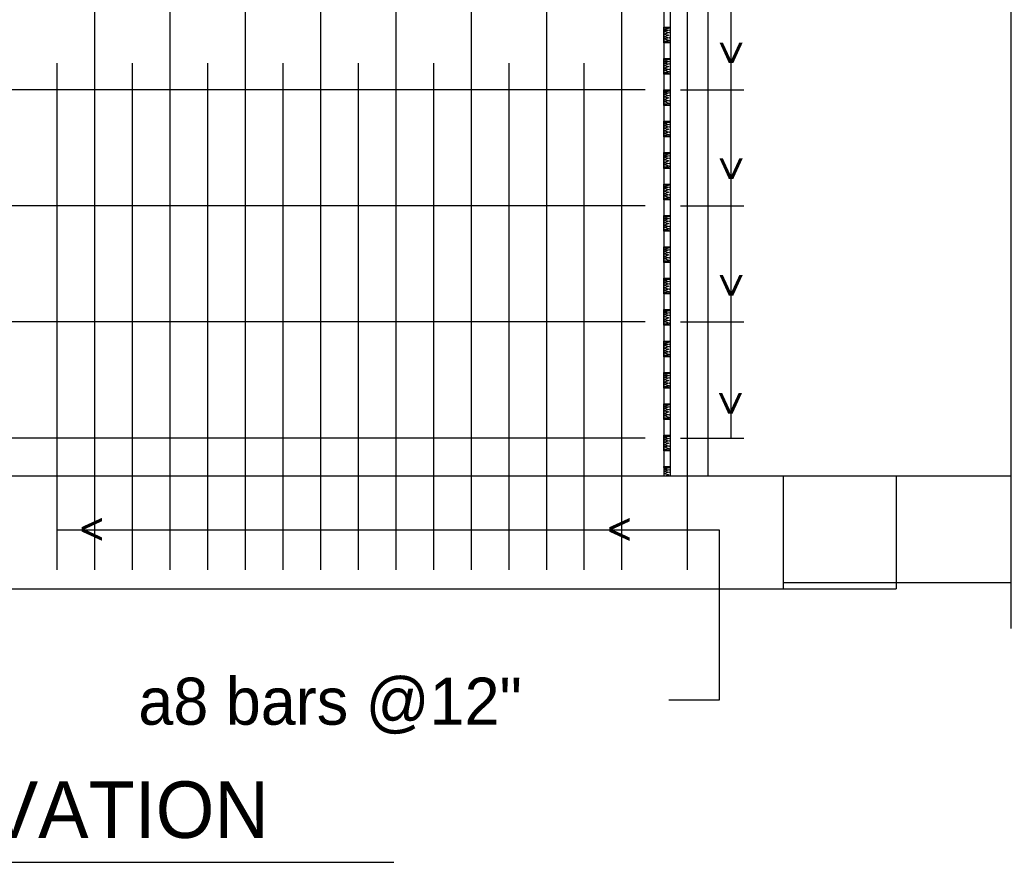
# Model space of a CAD drawing. Extents: x -0.08 to 2.83, y -0.03 to 1.92.
# Drawn here: x 0.6457 to 0.9199, y 0.5697 to 0.8025 of the extents above; entities that cross this region are included whole.
import ezdxf

# ---------------------------------------------------------------- set-up
doc = ezdxf.new("R2010")
doc.units = 0
for name, color, linetype in [('1', 7, 'Continuous'), ('50', 7, 'Continuous'), ('51', 7, 'Continuous'), ('55', 7, 'Continuous'), ('57', 7, 'Continuous')]:
    doc.layers.add(name, color=color, linetype=linetype)

msp = doc.modelspace()

# ---------------------------------------------------------------- linework, layer by layer
at = {"layer": '1'}
for points in [[(0.82387, 0.79621), (0.82387, 0.80055), (0.8256, 0.80055), (0.8256, 0.79621)], [(0.82387, 0.78754), (0.82387, 0.79187), (0.8256, 0.79187), (0.8256, 0.78754)], [(0.82387, 0.77885), (0.82387, 0.78319), (0.8256, 0.78319), (0.8256, 0.77885)], [(0.82387, 0.77017), (0.82387, 0.77451), (0.8256, 0.77451), (0.8256, 0.77017)], [(0.82387, 0.76149), (0.82387, 0.76583), (0.8256, 0.76583), (0.8256, 0.76149)], [(0.82387, 0.75281), (0.82387, 0.75714), (0.8256, 0.75714), (0.8256, 0.75281)], [(0.82387, 0.74413), (0.82387, 0.74847), (0.8256, 0.74847), (0.8256, 0.74413)], [(0.82387, 0.73545), (0.82387, 0.73979), (0.8256, 0.73979), (0.8256, 0.73545)], [(0.82387, 0.72677), (0.82387, 0.7311), (0.8256, 0.7311), (0.8256, 0.72677)], [(0.82387, 0.71809), (0.82387, 0.72243), (0.8256, 0.72243), (0.8256, 0.71809)], [(0.82387, 0.70941), (0.82387, 0.71374), (0.8256, 0.71374), (0.8256, 0.70941)], [(0.82387, 0.70073), (0.82387, 0.70506), (0.8256, 0.70506), (0.8256, 0.70073)], [(0.82387, 0.69204), (0.82387, 0.69639), (0.8256, 0.69639), (0.8256, 0.69204)], [(0.82387, 0.68337), (0.82387, 0.6877), (0.8256, 0.6877), (0.8256, 0.68337)]]:
    msp.add_lwpolyline(points, close=True, dxfattribs=at)
for points in [[(0.82398, 0.80031), (0.8255, 0.80033), (0.82398, 0.7998), (0.82534, 0.79969), (0.82402, 0.79928), (0.82531, 0.79901), (0.82405, 0.79861), (0.82526, 0.79832), (0.82405, 0.79787), (0.82536, 0.79754), (0.82401, 0.7973), (0.82536, 0.79681), (0.82409, 0.79657), (0.82531, 0.79645), (0.82524, 0.79644)], [(0.82398, 0.79163), (0.8255, 0.79164), (0.82398, 0.79112), (0.82534, 0.791), (0.82402, 0.7906), (0.82531, 0.79034), (0.82405, 0.78993), (0.82526, 0.78964), (0.82405, 0.78919), (0.82536, 0.78886), (0.82401, 0.78862), (0.82536, 0.78813), (0.82409, 0.78789), (0.82531, 0.78777), (0.82524, 0.78775)], [(0.82398, 0.78294), (0.8255, 0.78296), (0.82398, 0.78244), (0.82534, 0.78233), (0.82402, 0.78192), (0.82531, 0.78165), (0.82405, 0.78125), (0.82526, 0.78095), (0.82405, 0.7805), (0.82536, 0.78018), (0.82401, 0.77994), (0.82536, 0.77944), (0.82409, 0.77921), (0.82531, 0.77909), (0.82524, 0.77908)], [(0.82398, 0.77427), (0.8255, 0.77429), (0.82398, 0.77376), (0.82534, 0.77364), (0.82402, 0.77324), (0.82531, 0.77297), (0.82405, 0.77257), (0.82526, 0.77228), (0.82405, 0.77183), (0.82536, 0.77149), (0.82401, 0.77126), (0.82536, 0.77077), (0.82409, 0.77053), (0.82531, 0.77041), (0.82524, 0.77039)], [(0.82398, 0.76559), (0.8255, 0.7656), (0.82398, 0.76508), (0.82534, 0.76496), (0.82402, 0.76456), (0.82531, 0.76429), (0.82405, 0.76389), (0.82526, 0.76359), (0.82405, 0.76314), (0.82536, 0.76282), (0.82401, 0.76258), (0.82536, 0.76209), (0.82409, 0.76184), (0.82531, 0.76173), (0.82524, 0.76171)], [(0.82398, 0.7569), (0.8255, 0.75692), (0.82398, 0.7564), (0.82534, 0.75629), (0.82402, 0.75588), (0.82531, 0.75561), (0.82405, 0.75521), (0.82526, 0.75491), (0.82405, 0.75446), (0.82536, 0.75414), (0.82401, 0.75389), (0.82536, 0.7534), (0.82409, 0.75317), (0.82531, 0.75305), (0.82524, 0.75304)], [(0.82398, 0.74823), (0.8255, 0.74824), (0.82398, 0.74772), (0.82534, 0.7476), (0.82402, 0.74719), (0.82531, 0.74693), (0.82405, 0.74653), (0.82526, 0.74624), (0.82405, 0.74579), (0.82536, 0.74545), (0.82401, 0.74522), (0.82536, 0.74473), (0.82409, 0.74449), (0.82531, 0.74437), (0.82524, 0.74435)], [(0.82398, 0.73954), (0.8255, 0.73956), (0.82398, 0.73904), (0.82534, 0.73892), (0.82402, 0.73852), (0.82531, 0.73825), (0.82405, 0.73784), (0.82526, 0.73755), (0.82405, 0.7371), (0.82536, 0.73678), (0.82401, 0.73654), (0.82536, 0.73604), (0.82409, 0.7358), (0.82531, 0.73569), (0.82524, 0.73567)], [(0.82398, 0.73086), (0.8255, 0.73088), (0.82398, 0.73036), (0.82534, 0.73024), (0.82402, 0.72984), (0.82531, 0.72957), (0.82405, 0.72917), (0.82526, 0.72887), (0.82405, 0.72842), (0.82536, 0.72809), (0.82401, 0.72785), (0.82536, 0.72736), (0.82409, 0.72713), (0.82531, 0.72701), (0.82524, 0.72699)], [(0.82398, 0.72219), (0.8255, 0.7222), (0.82398, 0.72168), (0.82534, 0.72156), (0.82402, 0.72115), (0.82531, 0.72089), (0.82405, 0.72049), (0.82526, 0.72019), (0.82405, 0.71974), (0.82536, 0.71941), (0.82401, 0.71918), (0.82536, 0.71869), (0.82409, 0.71844), (0.82531, 0.71833), (0.82524, 0.71831)], [(0.82398, 0.7135), (0.8255, 0.71352), (0.82398, 0.71299), (0.82534, 0.71288), (0.82402, 0.71248), (0.82531, 0.71221), (0.82405, 0.7118), (0.82526, 0.71151), (0.82405, 0.71106), (0.82536, 0.71074), (0.82401, 0.71049), (0.82536, 0.71), (0.82409, 0.70976), (0.82531, 0.70964), (0.82524, 0.70963)], [(0.82398, 0.70482), (0.8255, 0.70484), (0.82398, 0.70432), (0.82534, 0.7042), (0.82402, 0.70379), (0.82531, 0.70353), (0.82405, 0.70313), (0.82526, 0.70283), (0.82405, 0.70238), (0.82536, 0.70205), (0.82401, 0.70181), (0.82536, 0.70132), (0.82409, 0.70109), (0.82531, 0.70097), (0.82524, 0.70095)], [(0.82398, 0.69614), (0.8255, 0.69616), (0.82398, 0.69564), (0.82534, 0.69552), (0.82402, 0.69511), (0.82531, 0.69484), (0.82405, 0.69444), (0.82526, 0.69415), (0.82405, 0.6937), (0.82536, 0.69337), (0.82401, 0.69314), (0.82536, 0.69264), (0.82409, 0.6924), (0.82531, 0.69229), (0.82524, 0.69227)], [(0.82398, 0.68746), (0.8255, 0.68748), (0.82398, 0.68695), (0.82534, 0.68684), (0.82402, 0.68644), (0.82531, 0.68617), (0.82405, 0.68576), (0.82526, 0.68547), (0.82405, 0.68502), (0.82536, 0.68469), (0.82401, 0.68445), (0.82536, 0.68396), (0.82409, 0.68372), (0.82531, 0.6836), (0.82524, 0.68359)], [(0.82387, 0.67877), (0.82387, 0.67902), (0.82552, 0.67902)], [(0.82398, 0.67878), (0.8255, 0.67879), (0.82398, 0.67828), (0.82534, 0.67816), (0.82402, 0.67775), (0.82531, 0.67749), (0.82405, 0.67709), (0.82526, 0.67679), (0.82444, 0.67649)]]:
    msp.add_lwpolyline(points, dxfattribs=at)
at = {"layer": '50'}
for p, q in [((0.83601, 0.99767), (0.83601, 0.67648)), ((0.82385, 0.90749), (0.82385, 0.67648)), ((0.82559, 0.90749), (0.82559, 0.67642)), ((0.91992, 0.63423), (0.91992, 0.81979)), ((0.82385, 0.80125), (0.82385, 0.79516)), ((0.82559, 0.80125), (0.82559, 0.79516)), ((0.82385, 0.80061), (0.82385, 0.79592)), ((0.82559, 0.80061), (0.82559, 0.79592)), ((0.82559, 0.80011), (0.82559, 0.79592)), ((0.82385, 0.79592), (0.82385, 0.79516)), ((0.82559, 0.79592), (0.82559, 0.79516)), ((0.82385, 0.79257), (0.82385, 0.78649)), ((0.82385, 0.79257), (0.82385, 0.78649)), ((0.82559, 0.79257), (0.82559, 0.78649)), ((0.82559, 0.79257), (0.82559, 0.78649)), ((0.82385, 0.79193), (0.82385, 0.78724)), ((0.82559, 0.79193), (0.82559, 0.78724)), ((0.82559, 0.79144), (0.82559, 0.78724)), ((0.82385, 0.78724), (0.82385, 0.78649)), ((0.82559, 0.78724), (0.82559, 0.78649)), ((0.82385, 0.78389), (0.82385, 0.7778)), ((0.82385, 0.78389), (0.82385, 0.7778)), ((0.82385, 0.78389), (0.82385, 0.7778)), ((0.82385, 0.78325), (0.82385, 0.77856)), ((0.82559, 0.78389), (0.82559, 0.7778)), ((0.82559, 0.78389), (0.82559, 0.7778)), ((0.82559, 0.78389), (0.82559, 0.7778)), ((0.82559, 0.78325), (0.82559, 0.77856)), ((0.82559, 0.78275), (0.82559, 0.77856)), ((0.82385, 0.77856), (0.82385, 0.7778)), ((0.82559, 0.77856), (0.82559, 0.7778)), ((0.82385, 0.77457), (0.82385, 0.76988)), ((0.82559, 0.77457), (0.82559, 0.76988)), ((0.82559, 0.77407), (0.82559, 0.76988)), ((0.82385, 0.76988), (0.82385, 0.76912)), ((0.82559, 0.76988), (0.82559, 0.76912)), ((0.82385, 0.76653), (0.82385, 0.76044)), ((0.82385, 0.76589), (0.82385, 0.76119)), ((0.82559, 0.76653), (0.82559, 0.76044)), ((0.82559, 0.76589), (0.82559, 0.76119)), ((0.82559, 0.76539), (0.82559, 0.76119)), ((0.82385, 0.76119), (0.82385, 0.76044)), ((0.82559, 0.76119), (0.82559, 0.76044)), ((0.82385, 0.75784), (0.82385, 0.75176)), ((0.82385, 0.75784), (0.82385, 0.75176)), ((0.82385, 0.75721), (0.82385, 0.75252)), ((0.82559, 0.75784), (0.82559, 0.75176)), ((0.82559, 0.75784), (0.82559, 0.75176)), ((0.82559, 0.75721), (0.82559, 0.75252)), ((0.82559, 0.75671), (0.82559, 0.75252)), ((0.82385, 0.75252), (0.82385, 0.75176)), ((0.82559, 0.75252), (0.82559, 0.75176)), ((0.82385, 0.74917), (0.82385, 0.74308)), ((0.82385, 0.74917), (0.82385, 0.74308)), ((0.82385, 0.74917), (0.82385, 0.74308)), ((0.82559, 0.74917), (0.82559, 0.74308)), ((0.82559, 0.74917), (0.82559, 0.74308)), ((0.82559, 0.74917), (0.82559, 0.74308)), ((0.82385, 0.74853), (0.82385, 0.74384)), ((0.82559, 0.74853), (0.82559, 0.74384)), ((0.82559, 0.74803), (0.82559, 0.74384)), ((0.82385, 0.74384), (0.82385, 0.74308)), ((0.82559, 0.74384), (0.82559, 0.74308)), ((0.82385, 0.73984), (0.82385, 0.73515)), ((0.82559, 0.73984), (0.82559, 0.73515)), ((0.82559, 0.73935), (0.82559, 0.73515)), ((0.82385, 0.73515), (0.82385, 0.7344)), ((0.82559, 0.73515), (0.82559, 0.7344)), ((0.82385, 0.7318), (0.82385, 0.72572)), ((0.82385, 0.73117), (0.82385, 0.72648)), ((0.82559, 0.7318), (0.82559, 0.72572)), ((0.82559, 0.73117), (0.82559, 0.72648)), ((0.82559, 0.73067), (0.82559, 0.72648)), ((0.82385, 0.72648), (0.82385, 0.72572)), ((0.82559, 0.72648), (0.82559, 0.72572)), ((0.82385, 0.72313), (0.82385, 0.71704)), ((0.82385, 0.72313), (0.82385, 0.71704)), ((0.82385, 0.72249), (0.82385, 0.71779)), ((0.82559, 0.72313), (0.82559, 0.71704)), ((0.82559, 0.72313), (0.82559, 0.71704)), ((0.82559, 0.72249), (0.82559, 0.71779)), ((0.82559, 0.72199), (0.82559, 0.71779)), ((0.82385, 0.71779), (0.82385, 0.71704)), ((0.82559, 0.71779), (0.82559, 0.71704)), ((0.82385, 0.71444), (0.82385, 0.70836)), ((0.82385, 0.71444), (0.82385, 0.70836)), ((0.82385, 0.71444), (0.82385, 0.70836)), ((0.82385, 0.7138), (0.82385, 0.70911)), ((0.82559, 0.71444), (0.82559, 0.70836)), ((0.82559, 0.71444), (0.82559, 0.70836)), ((0.82559, 0.71444), (0.82559, 0.70836)), ((0.82559, 0.7138), (0.82559, 0.70911)), ((0.82559, 0.71331), (0.82559, 0.70911)), ((0.82385, 0.70911), (0.82385, 0.70836)), ((0.82559, 0.70911), (0.82559, 0.70836)), ((0.82385, 0.70513), (0.82385, 0.70044)), ((0.82559, 0.70513), (0.82559, 0.70044)), ((0.82559, 0.70463), (0.82559, 0.70044)), ((0.82385, 0.70044), (0.82385, 0.69968)), ((0.82559, 0.70044), (0.82559, 0.69968)), ((0.82385, 0.69709), (0.82385, 0.69099)), ((0.82559, 0.69709), (0.82559, 0.69099)), ((0.82385, 0.69644), (0.82385, 0.69175)), ((0.82559, 0.69644), (0.82559, 0.69175)), ((0.82559, 0.69594), (0.82559, 0.69175)), ((0.82385, 0.69175), (0.82385, 0.69099)), ((0.82559, 0.69175), (0.82559, 0.69099)), ((0.82385, 0.6884), (0.82385, 0.68232)), ((0.82385, 0.6884), (0.82385, 0.68232)), ((0.82559, 0.6884), (0.82559, 0.68232)), ((0.82559, 0.6884), (0.82559, 0.68232)), ((0.82385, 0.68776), (0.82385, 0.68307)), ((0.82559, 0.68776), (0.82559, 0.68307)), ((0.82559, 0.68727), (0.82559, 0.68307)), ((0.82385, 0.68307), (0.82385, 0.68232)), ((0.82559, 0.68307), (0.82559, 0.68232)), ((0.36955, 0.67649), (0.91992, 0.67649)), ((0.82559, 0.67649), (0.82559, 0.67638)), ((0.85684, 0.67648), (0.85684, 0.64523)), ((0.88809, 0.67649), (0.88809, 0.64524)), ((0.36955, 0.64524), (0.88809, 0.64524)), ((0.85684, 0.64697), (0.91992, 0.64697))]:
    msp.add_line(p, q, dxfattribs=at)
at = {"layer": '51'}
for p, q in [((0.81226, 0.65044), (0.81226, 0.98682)), ((0.83039, 0.65044), (0.83039, 0.98682)), ((0.74976, 0.65044), (0.74976, 0.96326)), ((0.77059, 0.65044), (0.77059, 0.96326)), ((0.79143, 0.65044), (0.79143, 0.96326)), ((0.68726, 0.65044), (0.68726, 0.94275)), ((0.70809, 0.65044), (0.70809, 0.94275)), ((0.72893, 0.65044), (0.72893, 0.94275)), ((0.66643, 0.65044), (0.66643, 0.92069)), ((0.65601, 0.65044), (0.65601, 0.7906)), ((0.67684, 0.65044), (0.67684, 0.7906)), ((0.69768, 0.65044), (0.69768, 0.7906)), ((0.71851, 0.65044), (0.71851, 0.7906)), ((0.73934, 0.65044), (0.73934, 0.7906)), ((0.76018, 0.65044), (0.76018, 0.7906)), ((0.78101, 0.65044), (0.78101, 0.7906)), ((0.80184, 0.65044), (0.80184, 0.7906)), ((0.81864, 0.78324), (0.37281, 0.78324)), ((0.82847, 0.78324), (0.84599, 0.78324)), ((0.84122, 0.78325), (0.84122, 0.78325)), ((0.81864, 0.75113), (0.37281, 0.75113)), ((0.82847, 0.75113), (0.84599, 0.75113)), ((0.84122, 0.75113), (0.84122, 0.75113)), ((0.81864, 0.71901), (0.37281, 0.71901)), ((0.82847, 0.71901), (0.84599, 0.71901)), ((0.84122, 0.71901), (0.84122, 0.71901)), ((0.81864, 0.68689), (0.37281, 0.68689)), ((0.82847, 0.68689), (0.84599, 0.68689)), ((0.84122, 0.68689), (0.84122, 0.68689))]:
    msp.add_line(p, q, dxfattribs=at)
at = {"layer": '55'}
for p, q in [((0.84244, 0.68689), (0.84244, 0.97595)), ((0.65601, 0.6615), (0.83918, 0.6615)), ((0.83918, 0.6615), (0.83918, 0.61445)), ((0.83918, 0.61445), (0.82519, 0.61445))]:
    msp.add_line(p, q, dxfattribs=at)
at = {"layer": '57'}
msp.add_line((0.52505, 0.56966), (0.74916, 0.56966), dxfattribs=at)

# ---------------------------------------------------------------- texts
at = {"layer": '55'}
for rotation, p in [(270, (0.83829, 0.79683)), (270, (0.83829, 0.79683)), (270, (0.83829, 0.76479)), (270, (0.83829, 0.76479)), (270, (0.83829, 0.73254)), (270, (0.83829, 0.73254)), (270, (0.8381, 0.69991)), (270, (0.8381, 0.69991)), (180, (0.66903, 0.66584)), (180, (0.66903, 0.66584)), (180, (0.66903, 0.66584)), (180, (0.66903, 0.66584)), (180, (0.81499, 0.6658)), (180, (0.81499, 0.6658))]:
    msp.add_text('>', height=0.00868, rotation=rotation, dxfattribs=at).set_placement(p)
at = {"layer": '57'}
for s, height, p in [('a8 bars @12"', 0.0130167, (0.67847, 0.60766)), ('WING ELEVATION', 0.015625, (0.53466, 0.57637))]:
    msp.add_text(s, height=height, dxfattribs=at).set_placement(p)

doc.saveas('drawing.dxf')
